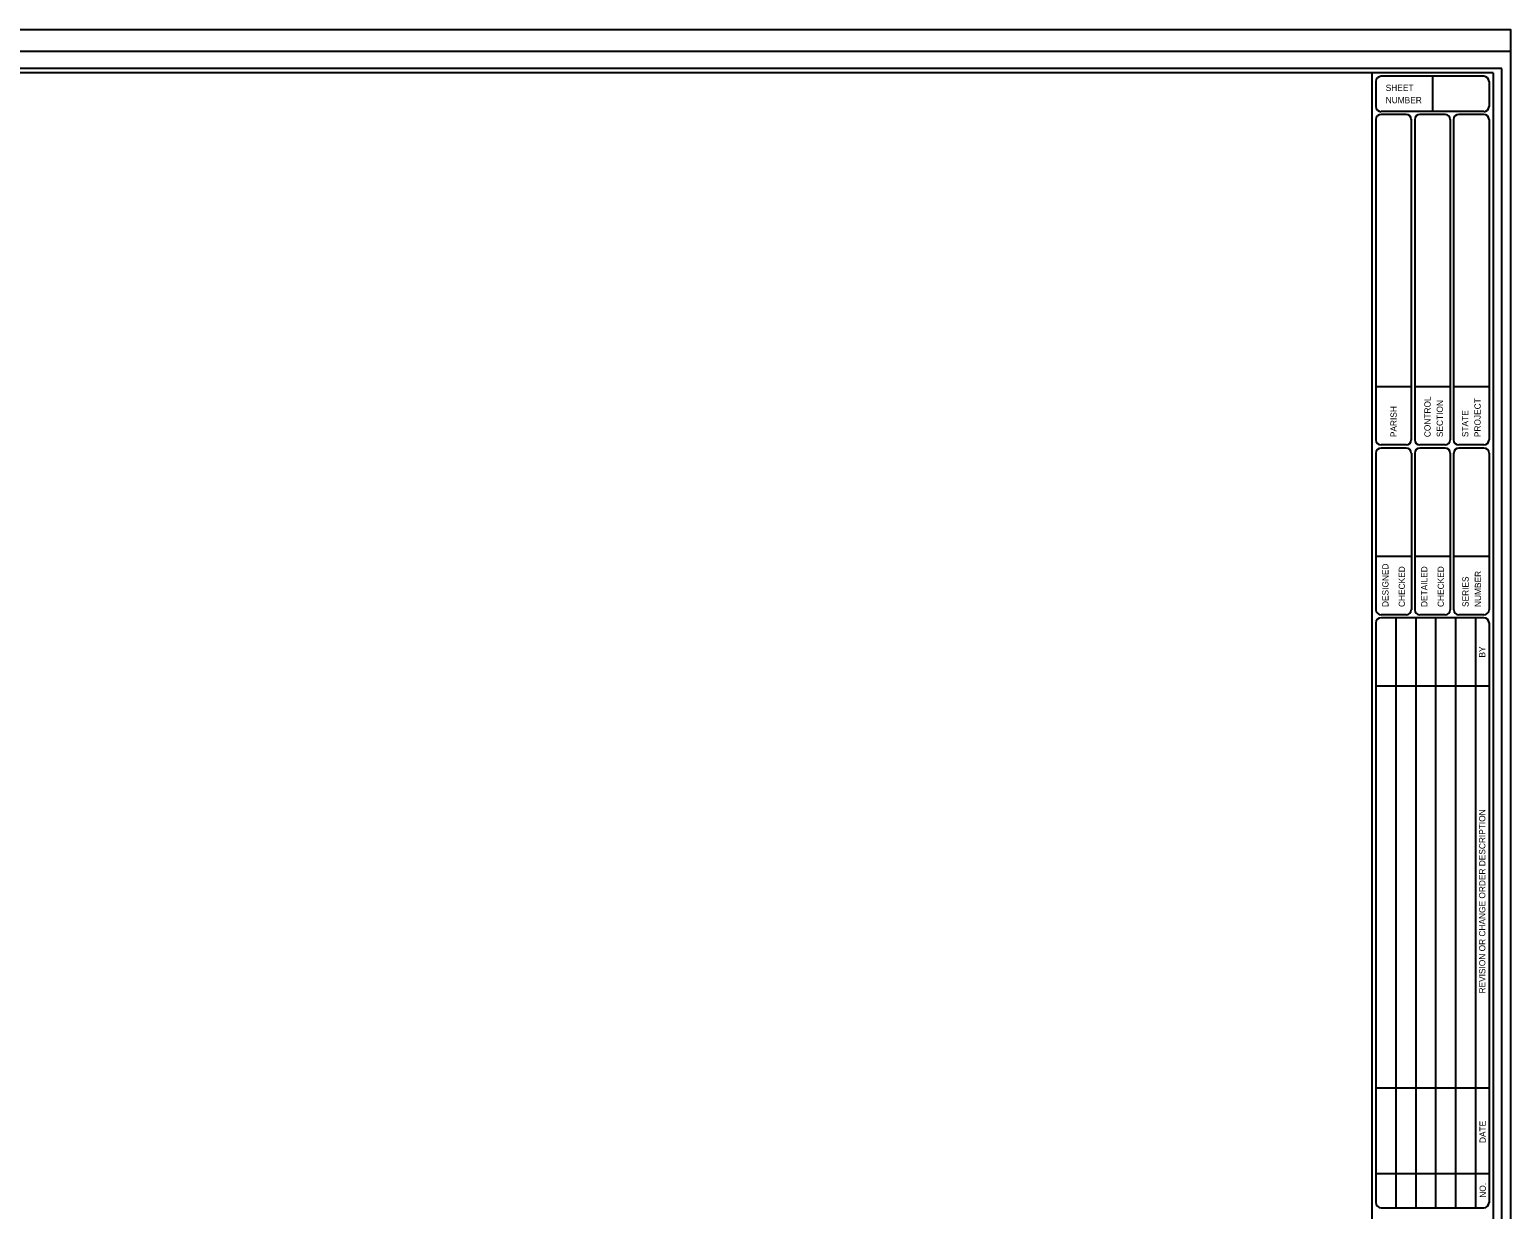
# Model space of a CAD drawing. Extents: x -0.02 to 2.83, y -0.02 to 1.85.
# Drawn here: x 1.408 to 2.833, y 0.697 to 1.833 of the extents above; entities that cross this region are included whole.
import ezdxf

# ---------------------------------------------------------------- set-up
doc = ezdxf.new("R2010")
doc.units = 0
for name, color, linetype in [('Plot Border', 7, 'Continuous'), ('Plot Border 2', 7, 'Continuous'), ('Sheet Border', 7, 'Continuous')]:
    doc.layers.add(name, color=color, linetype=linetype)

msp = doc.modelspace()

# ---------------------------------------------------------------- linework, layer by layer
at = {"layer": 'Plot Border'}
for points in [[(0, 1.8333), (2.8333, 1.8333), (2.8333, 0), (0, 0)], [(2.825, 1.7958), (0.075, 1.7958), (0.075, 0.0375), (2.825, 0.0375)]]:
    msp.add_lwpolyline(points, close=True, dxfattribs=at)
at = {"layer": 'Plot Border 2'}
msp.add_lwpolyline([(0, 1.8125), (2.8333, 1.8125), (2.8333, 0.0208), (0, 0.0208)], close=True, dxfattribs=at)
at = {"layer": 'Sheet Border'}
for p, q in [((2.8167, 1.7917), (0.1917, 1.7917)), ((2.7, 1.7917), (2.7, 0.0417)), ((2.7039, 1.7834), (2.7039, 1.7592)), ((2.8079, 1.7884), (2.7088, 1.7884)), ((2.7583, 1.7884), (2.7583, 1.7543)), ((2.8128, 1.7834), (2.8128, 1.7592)), ((2.8167, 1.7917), (2.8167, 0.0417)), ((2.8079, 1.7543), (2.7088, 1.7543)), ((2.7039, 1.747), (2.7039, 1.4379)), ((2.733, 1.7516), (2.7088, 1.7516)), ((2.7379, 1.7471), (2.7379, 1.4378)), ((2.7412, 1.7467), (2.7412, 1.4382)), ((2.7704, 1.7516), (2.7462, 1.7516)), ((2.7754, 1.7467), (2.7754, 1.4382)), ((2.7787, 1.7467), (2.7787, 1.4382)), ((2.8079, 1.7516), (2.7836, 1.7516)), ((2.8128, 1.7467), (2.8128, 1.4382)), ((2.7379, 1.4894), (2.7039, 1.4894)), ((2.7754, 1.4894), (2.7412, 1.4894)), ((2.8128, 1.4894), (2.7787, 1.4894)), ((2.7039, 1.4257), (2.7039, 1.2746)), ((2.733, 1.4333), (2.7088, 1.4333)), ((2.733, 1.4302), (2.7088, 1.4302)), ((2.7413, 1.4257), (2.7413, 1.2746)), ((2.7704, 1.4333), (2.7462, 1.4333)), ((2.7705, 1.4302), (2.7462, 1.4302)), ((2.7787, 1.4257), (2.7787, 1.2746)), ((2.8079, 1.4333), (2.7836, 1.4333)), ((2.8079, 1.4302), (2.7837, 1.4302)), ((2.738, 1.4253), (2.738, 1.2746)), ((2.7754, 1.4253), (2.7754, 1.2746)), ((2.8129, 1.4253), (2.8129, 1.2746)), ((2.7379, 1.3258), (2.7039, 1.3258)), ((2.7754, 1.3258), (2.7412, 1.3258)), ((2.8128, 1.3258), (2.7787, 1.3258)), ((2.733, 1.2697), (2.7088, 1.2697)), ((2.7705, 1.2697), (2.7462, 1.2697)), ((2.8079, 1.2697), (2.7837, 1.2697)), ((2.7039, 1.2619), (2.7039, 0.7034)), ((2.8079, 1.2668), (2.7088, 1.2668)), ((2.723, 1.2668), (2.723, 0.6985)), ((2.7422, 1.2668), (2.7422, 0.6985)), ((2.7613, 1.2668), (2.7613, 0.6985)), ((2.7805, 1.2668), (2.7805, 0.6985)), ((2.7996, 1.2668), (2.7996, 0.6985)), ((2.8128, 1.2619), (2.8128, 0.7034)), ((2.8128, 1.2008), (2.7039, 1.2008)), ((2.7039, 0.8141), (2.8128, 0.8141)), ((2.7039, 0.7315), (2.8128, 0.7315)), ((2.7088, 0.6985), (2.8079, 0.6985))]:
    msp.add_line(p, q, dxfattribs=at)
for centre, start, end in [((2.7088, 1.7834), 90, 180), ((2.8078, 1.7834), 0, 90), ((2.7088, 1.7592), 180, 270), ((2.8078, 1.7592), 270, 0), ((2.7088, 1.7467), 90, 180), ((2.733, 1.7467), 0, 90), ((2.7462, 1.7467), 90, 180), ((2.7704, 1.7467), 0, 90), ((2.7836, 1.7467), 90, 180), ((2.8078, 1.7467), 0, 90), ((2.7088, 1.4382), 180, 270), ((2.7088, 1.4253), 90, 180), ((2.733, 1.4382), 270, 0), ((2.733, 1.4253), 0, 90), ((2.7462, 1.4382), 180, 270), ((2.7462, 1.4253), 90, 180), ((2.7704, 1.4382), 270, 0), ((2.7705, 1.4253), 0, 90), ((2.7836, 1.4382), 180, 270), ((2.7837, 1.4253), 90, 180), ((2.8078, 1.4382), 270, 0), ((2.8079, 1.4253), 0, 90), ((2.7088, 1.2746), 180, 270), ((2.733, 1.2746), 270, 0), ((2.7462, 1.2746), 180, 270), ((2.7705, 1.2746), 270, 0), ((2.7837, 1.2746), 180, 270), ((2.8079, 1.2746), 270, 0), ((2.7088, 1.2619), 90, 180), ((2.8078, 1.2619), 0, 90), ((2.7088, 0.7035), 180, 270), ((2.8078, 0.7035), 270, 0)]:
    msp.add_arc(centre, 0.00495, start, end, dxfattribs=at)

# ---------------------------------------------------------------- texts
for s, p in [('SHEET', (2.7133, 1.7743)), ('NUMBER', (2.7133, 1.7624))]:
    msp.add_text(s, height=0.006, dxfattribs=at).set_placement(p)
for s, p in [('PARISH', (2.7239, 1.4408)), ('CONTROL', (2.7565, 1.4408)), ('SECTION', (2.7684, 1.4408)), ('PROJECT', (2.8047, 1.4408)), ('STATE', (2.7928, 1.4408)), ('DESIGNED', (2.716, 1.2772)), ('CHECKED', (2.7318, 1.2772)), ('DETAILED', (2.7534, 1.2772)), ('CHECKED', (2.7693, 1.2772)), ('NUMBER', (2.8051, 1.2772)), ('SERIES', (2.7931, 1.2772)), ('BY', (2.8092, 1.2285)), ('REVISION OR CHANGE ORDER DESCRIPTION', (2.8092, 0.9049)), ('DATE', (2.8096, 0.7609)), ('NO.', (2.8097, 0.7082))]:
    msp.add_text(s, height=0.006, rotation=90, dxfattribs=at).set_placement(p)

doc.saveas('drawing.dxf')
